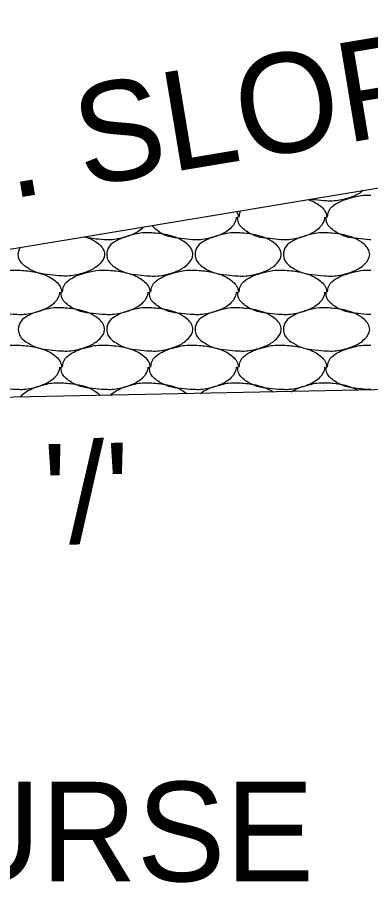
# Model space of a CAD drawing. Extents: x 1364961 to 1365294, y 367927 to 368034.
# Drawn here: x 1365019.89 to 1365021.94, y 367994.89 to 367999.9 of the extents above; entities that cross this region are included whole.
import ezdxf

# ---------------------------------------------------------------- set-up
doc = ezdxf.new("R2010")
doc.units = 0
doc.layers.add('Default', color=7, linetype='Continuous')

msp = doc.modelspace()

# ---------------------------------------------------------------- linework, layer by layer
at = {"layer": 'Default'}
for p, q in [((1365025.9943, 367999.5737), (1365004.6394, 367996.027)), ((1365019.8943, 367998.4337), (1365019.9003, 367998.4337)), ((1365020.4063, 367998.4337), (1365020.4123, 367998.4337)), ((1365020.9183, 367998.4337), (1365020.9243, 367998.4337)), ((1365021.4303, 367998.4337), (1365021.4363, 367998.4337)), ((1365019.8943, 367997.9997), (1365019.9003, 367997.9997)), ((1365020.4063, 367997.9997), (1365020.4123, 367997.9997)), ((1365020.9183, 367997.9997), (1365020.9243, 367997.9997)), ((1365021.4303, 367997.9997), (1365021.4363, 367997.9997)), ((1365031.9783, 367997.9397), (1365013.9943, 367997.5807))]:
    msp.add_line(p, q, dxfattribs=at)
for points in [[(1365021.8983, 367998.8937), (1365021.8783, 367998.8797), (1365021.8163, 367998.8517), (1365021.7303, 367998.8337), (1365021.6863, 367998.8337), (1365021.6203, 367998.8397), (1365021.5943, 367998.8427)], [(1365021.6923, 367998.7397), (1365021.6923, 367998.7417), (1365021.7083, 367998.7897), (1365021.7483, 367998.8217), (1365021.7883, 367998.8397), (1365021.8483, 367998.8577), (1365021.8863, 367998.8657), (1365021.9423, 367998.8677)], [(1365021.5833, 367998.8407), (1365021.6263, 367998.8217), (1365021.6783, 367998.7717), (1365021.6863, 367998.7417), (1365021.6863, 367998.7397)], [(1365021.1663, 367998.7717), (1365021.1743, 367998.7417), (1365021.1743, 367998.7397)], [(1365021.1803, 367998.7397), (1365021.1803, 367998.7417), (1365021.1883, 367998.7757)], [(1365021.1623, 367998.7397), (1365021.1623, 367998.7337), (1365021.1343, 367998.6797), (1365021.1043, 367998.6557), (1365021.0423, 367998.6277), (1365020.9563, 367998.6097), (1365020.9183, 367998.6097)], [(1365021.4303, 367998.6097), (1365021.4223, 367998.6097), (1365021.3563, 367998.6157), (1365021.2843, 367998.6277), (1365021.2303, 367998.6537), (1365021.1803, 367998.6997), (1365021.1723, 367998.7337), (1365021.1723, 367998.7397)], [(1365021.6743, 367998.7397), (1365021.6743, 367998.7337), (1365021.6463, 367998.6797), (1365021.6163, 367998.6557), (1365021.5543, 367998.6277), (1365021.4683, 367998.6097), (1365021.4303, 367998.6097)], [(1365021.9423, 367998.6097), (1365021.9343, 367998.6097), (1365021.8683, 367998.6157), (1365021.7963, 367998.6277), (1365021.7423, 367998.6537), (1365021.6923, 367998.6997), (1365021.6843, 367998.7337), (1365021.6843, 367998.7397)], [(1365020.6243, 367998.6817), (1365020.6223, 367998.6797), (1365020.5923, 367998.6557), (1365020.5303, 367998.6277), (1365020.4443, 367998.6097), (1365020.4063, 367998.6097)], [(1365020.6623, 367998.6497), (1365020.7503, 367998.6397), (1365020.8523, 367998.6037), (1365020.9043, 367998.5537), (1365020.9123, 367998.5237), (1365020.8843, 367998.4697), (1365020.8543, 367998.4457), (1365020.7923, 367998.4177), (1365020.7063, 367998.3997), (1365020.6623, 367998.3997), (1365020.5963, 367998.4057), (1365020.5243, 367998.4177), (1365020.4703, 367998.4437), (1365020.4203, 367998.4897), (1365020.4123, 367998.5237), (1365020.4283, 367998.5717), (1365020.4683, 367998.6037), (1365020.5083, 367998.6217), (1365020.5683, 367998.6397), (1365020.6063, 367998.6477), (1365020.6623, 367998.6497)], [(1365020.9183, 367998.6097), (1365020.9103, 367998.6097), (1365020.8443, 367998.6157), (1365020.7723, 367998.6277), (1365020.7183, 367998.6537), (1365020.6743, 367998.6897)], [(1365021.1743, 367998.6497), (1365021.2623, 367998.6397), (1365021.3643, 367998.6037), (1365021.4163, 367998.5537), (1365021.4243, 367998.5237), (1365021.3963, 367998.4697), (1365021.3663, 367998.4457), (1365021.3043, 367998.4177), (1365021.2183, 367998.3997), (1365021.1743, 367998.3997), (1365021.1083, 367998.4057), (1365021.0363, 367998.4177), (1365020.9823, 367998.4437), (1365020.9323, 367998.4897), (1365020.9243, 367998.5237), (1365020.9403, 367998.5717), (1365020.9803, 367998.6037), (1365021.0203, 367998.6217), (1365021.0803, 367998.6397), (1365021.1183, 367998.6477), (1365021.1743, 367998.6497)], [(1365021.6863, 367998.6497), (1365021.7743, 367998.6397), (1365021.8763, 367998.6037), (1365021.9283, 367998.5537), (1365021.9363, 367998.5237), (1365021.9083, 367998.4697), (1365021.8783, 367998.4457), (1365021.8163, 367998.4177), (1365021.7303, 367998.3997), (1365021.6863, 367998.3997), (1365021.6203, 367998.4057), (1365021.5483, 367998.4177), (1365021.4943, 367998.4437), (1365021.4443, 367998.4897), (1365021.4363, 367998.5237), (1365021.4523, 367998.5717), (1365021.4923, 367998.6037), (1365021.5323, 367998.6217), (1365021.5923, 367998.6397), (1365021.6303, 367998.6477), (1365021.6863, 367998.6497)], [(1365020.2893, 367998.6257), (1365020.3403, 367998.6037), (1365020.3923, 367998.5537), (1365020.4003, 367998.5237), (1365020.3723, 367998.4697), (1365020.3423, 367998.4457), (1365020.2803, 367998.4177), (1365020.1943, 367998.3997), (1365020.1503, 367998.3997), (1365020.0843, 367998.4057), (1365020.0123, 367998.4177), (1365019.9583, 367998.4437), (1365019.9083, 367998.4897), (1365019.9003, 367998.5237), (1365019.9113, 367998.5637)], [(1365020.4063, 367998.6097), (1365020.3983, 367998.6097), (1365020.3323, 367998.6157), (1365020.2773, 367998.6237)], [(1365019.6443, 367998.3057), (1365019.6443, 367998.3077), (1365019.6603, 367998.3557), (1365019.7003, 367998.3877), (1365019.7403, 367998.4057), (1365019.8003, 367998.4237), (1365019.8383, 367998.4317), (1365019.8943, 367998.4337)], [(1365019.9003, 367998.4337), (1365019.9883, 367998.4237), (1365020.0903, 367998.3877), (1365020.1423, 367998.3377), (1365020.1503, 367998.3077), (1365020.1503, 367998.3057)], [(1365020.1563, 367998.3057), (1365020.1563, 367998.3077), (1365020.1723, 367998.3557), (1365020.2123, 367998.3877), (1365020.2523, 367998.4057), (1365020.3123, 367998.4237), (1365020.3503, 367998.4317), (1365020.4063, 367998.4337)], [(1365020.4123, 367998.4337), (1365020.5003, 367998.4237), (1365020.6023, 367998.3877), (1365020.6543, 367998.3377), (1365020.6623, 367998.3077), (1365020.6623, 367998.3057)], [(1365020.6683, 367998.3057), (1365020.6683, 367998.3077), (1365020.6843, 367998.3557), (1365020.7243, 367998.3877), (1365020.7643, 367998.4057), (1365020.8243, 367998.4237), (1365020.8623, 367998.4317), (1365020.9183, 367998.4337)], [(1365020.9243, 367998.4337), (1365021.0123, 367998.4237), (1365021.1143, 367998.3877), (1365021.1663, 367998.3377), (1365021.1743, 367998.3077), (1365021.1743, 367998.3057)], [(1365021.1803, 367998.3057), (1365021.1803, 367998.3077), (1365021.1963, 367998.3557), (1365021.2363, 367998.3877), (1365021.2763, 367998.4057), (1365021.3363, 367998.4237), (1365021.3743, 367998.4317), (1365021.4303, 367998.4337)], [(1365021.4363, 367998.4337), (1365021.5243, 367998.4237), (1365021.6263, 367998.3877), (1365021.6783, 367998.3377), (1365021.6863, 367998.3077), (1365021.6863, 367998.3057)], [(1365021.6923, 367998.3057), (1365021.6923, 367998.3077), (1365021.7083, 367998.3557), (1365021.7483, 367998.3877), (1365021.7883, 367998.4057), (1365021.8483, 367998.4237), (1365021.8863, 367998.4317), (1365021.9423, 367998.4337)], [(1365019.8943, 367998.1757), (1365019.8863, 367998.1757), (1365019.8203, 367998.1817), (1365019.7483, 367998.1937), (1365019.6943, 367998.2197), (1365019.6443, 367998.2657), (1365019.6363, 367998.2997), (1365019.6363, 367998.3057)], [(1365020.1383, 367998.3057), (1365020.1383, 367998.2997), (1365020.1103, 367998.2457), (1365020.0803, 367998.2217), (1365020.0183, 367998.1937), (1365019.9323, 367998.1757), (1365019.8943, 367998.1757)], [(1365020.4063, 367998.1757), (1365020.3983, 367998.1757), (1365020.3323, 367998.1817), (1365020.2603, 367998.1937), (1365020.2063, 367998.2197), (1365020.1563, 367998.2657), (1365020.1483, 367998.2997), (1365020.1483, 367998.3057)], [(1365020.6503, 367998.3057), (1365020.6503, 367998.2997), (1365020.6223, 367998.2457), (1365020.5923, 367998.2217), (1365020.5303, 367998.1937), (1365020.4443, 367998.1757), (1365020.4063, 367998.1757)], [(1365020.9183, 367998.1757), (1365020.9103, 367998.1757), (1365020.8443, 367998.1817), (1365020.7723, 367998.1937), (1365020.7183, 367998.2197), (1365020.6683, 367998.2657), (1365020.6603, 367998.2997), (1365020.6603, 367998.3057)], [(1365021.1623, 367998.3057), (1365021.1623, 367998.2997), (1365021.1343, 367998.2457), (1365021.1043, 367998.2217), (1365021.0423, 367998.1937), (1365020.9563, 367998.1757), (1365020.9183, 367998.1757)], [(1365021.4303, 367998.1757), (1365021.4223, 367998.1757), (1365021.3563, 367998.1817), (1365021.2843, 367998.1937), (1365021.2303, 367998.2197), (1365021.1803, 367998.2657), (1365021.1723, 367998.2997), (1365021.1723, 367998.3057)], [(1365021.6743, 367998.3057), (1365021.6743, 367998.2997), (1365021.6463, 367998.2457), (1365021.6163, 367998.2217), (1365021.5543, 367998.1937), (1365021.4683, 367998.1757), (1365021.4303, 367998.1757)], [(1365021.9423, 367998.1757), (1365021.9343, 367998.1757), (1365021.8683, 367998.1817), (1365021.7963, 367998.1937), (1365021.7423, 367998.2197), (1365021.6923, 367998.2657), (1365021.6843, 367998.2997), (1365021.6843, 367998.3057)], [(1365020.1503, 367998.2157), (1365020.2383, 367998.2057), (1365020.3403, 367998.1697), (1365020.3923, 367998.1197), (1365020.4003, 367998.0897), (1365020.3723, 367998.0357), (1365020.3423, 367998.0117), (1365020.2803, 367997.9837), (1365020.1943, 367997.9657), (1365020.1503, 367997.9657), (1365020.0843, 367997.9717), (1365020.0123, 367997.9837), (1365019.9583, 367998.0097), (1365019.9083, 367998.0557), (1365019.9003, 367998.0897), (1365019.9163, 367998.1377), (1365019.9563, 367998.1697), (1365019.9963, 367998.1877), (1365020.0563, 367998.2057), (1365020.0943, 367998.2137), (1365020.1503, 367998.2157)], [(1365020.6623, 367998.2157), (1365020.7503, 367998.2057), (1365020.8523, 367998.1697), (1365020.9043, 367998.1197), (1365020.9123, 367998.0897), (1365020.8843, 367998.0357), (1365020.8543, 367998.0117), (1365020.7923, 367997.9837), (1365020.7063, 367997.9657), (1365020.6623, 367997.9657), (1365020.5963, 367997.9717), (1365020.5243, 367997.9837), (1365020.4703, 367998.0097), (1365020.4203, 367998.0557), (1365020.4123, 367998.0897), (1365020.4283, 367998.1377), (1365020.4683, 367998.1697), (1365020.5083, 367998.1877), (1365020.5683, 367998.2057), (1365020.6063, 367998.2137), (1365020.6623, 367998.2157)], [(1365021.1743, 367998.2157), (1365021.2623, 367998.2057), (1365021.3643, 367998.1697), (1365021.4163, 367998.1197), (1365021.4243, 367998.0897), (1365021.3963, 367998.0357), (1365021.3663, 367998.0117), (1365021.3043, 367997.9837), (1365021.2183, 367997.9657), (1365021.1743, 367997.9657), (1365021.1083, 367997.9717), (1365021.0363, 367997.9837), (1365020.9823, 367998.0097), (1365020.9323, 367998.0557), (1365020.9243, 367998.0897), (1365020.9403, 367998.1377), (1365020.9803, 367998.1697), (1365021.0203, 367998.1877), (1365021.0803, 367998.2057), (1365021.1183, 367998.2137), (1365021.1743, 367998.2157)], [(1365021.6863, 367998.2157), (1365021.7743, 367998.2057), (1365021.8763, 367998.1697), (1365021.9283, 367998.1197), (1365021.9363, 367998.0897), (1365021.9083, 367998.0357), (1365021.8783, 367998.0117), (1365021.8163, 367997.9837), (1365021.7303, 367997.9657), (1365021.6863, 367997.9657), (1365021.6203, 367997.9717), (1365021.5483, 367997.9837), (1365021.4943, 367998.0097), (1365021.4443, 367998.0557), (1365021.4363, 367998.0897), (1365021.4523, 367998.1377), (1365021.4923, 367998.1697), (1365021.5323, 367998.1877), (1365021.5923, 367998.2057), (1365021.6303, 367998.2137), (1365021.6863, 367998.2157)], [(1365019.6443, 367997.8717), (1365019.6443, 367997.8737), (1365019.6603, 367997.9217), (1365019.7003, 367997.9537), (1365019.7403, 367997.9717), (1365019.8003, 367997.9897), (1365019.8383, 367997.9977), (1365019.8943, 367997.9997)], [(1365019.9003, 367997.9997), (1365019.9883, 367997.9897), (1365020.0903, 367997.9537), (1365020.1423, 367997.9037), (1365020.1503, 367997.8737), (1365020.1503, 367997.8717)], [(1365020.1563, 367997.8717), (1365020.1563, 367997.8737), (1365020.1723, 367997.9217), (1365020.2123, 367997.9537), (1365020.2523, 367997.9717), (1365020.3123, 367997.9897), (1365020.3503, 367997.9977), (1365020.4063, 367997.9997)], [(1365020.4123, 367997.9997), (1365020.5003, 367997.9897), (1365020.6023, 367997.9537), (1365020.6543, 367997.9037), (1365020.6623, 367997.8737), (1365020.6623, 367997.8717)], [(1365020.6683, 367997.8717), (1365020.6683, 367997.8737), (1365020.6843, 367997.9217), (1365020.7243, 367997.9537), (1365020.7643, 367997.9717), (1365020.8243, 367997.9897), (1365020.8623, 367997.9977), (1365020.9183, 367997.9997)], [(1365020.9243, 367997.9997), (1365021.0123, 367997.9897), (1365021.1143, 367997.9537), (1365021.1663, 367997.9037), (1365021.1743, 367997.8737), (1365021.1743, 367997.8717)], [(1365021.1803, 367997.8717), (1365021.1803, 367997.8737), (1365021.1963, 367997.9217), (1365021.2363, 367997.9537), (1365021.2763, 367997.9717), (1365021.3363, 367997.9897), (1365021.3743, 367997.9977), (1365021.4303, 367997.9997)], [(1365021.4363, 367997.9997), (1365021.5243, 367997.9897), (1365021.6263, 367997.9537), (1365021.6783, 367997.9037), (1365021.6863, 367997.8737), (1365021.6863, 367997.8717)], [(1365021.6923, 367997.8717), (1365021.6923, 367997.8737), (1365021.7083, 367997.9217), (1365021.7483, 367997.9537), (1365021.7883, 367997.9717), (1365021.8483, 367997.9897), (1365021.8863, 367997.9977), (1365021.9423, 367997.9997)], [(1365019.8943, 367997.7417), (1365019.8863, 367997.7417), (1365019.8203, 367997.7477), (1365019.7483, 367997.7597), (1365019.6943, 367997.7857), (1365019.6443, 367997.8317), (1365019.6363, 367997.8657), (1365019.6363, 367997.8717)], [(1365020.1383, 367997.8717), (1365020.1383, 367997.8657), (1365020.1103, 367997.8117), (1365020.0803, 367997.7877), (1365020.0183, 367997.7597), (1365019.9323, 367997.7417), (1365019.8943, 367997.7417)], [(1365020.4063, 367997.7417), (1365020.3983, 367997.7417), (1365020.3323, 367997.7477), (1365020.2603, 367997.7597), (1365020.2063, 367997.7857), (1365020.1563, 367997.8317), (1365020.1483, 367997.8657), (1365020.1483, 367997.8717)], [(1365020.6503, 367997.8717), (1365020.6503, 367997.8657), (1365020.6223, 367997.8117), (1365020.5923, 367997.7877), (1365020.5303, 367997.7597), (1365020.4443, 367997.7417), (1365020.4063, 367997.7417)], [(1365020.9183, 367997.7417), (1365020.9103, 367997.7417), (1365020.8443, 367997.7477), (1365020.7723, 367997.7597), (1365020.7183, 367997.7857), (1365020.6683, 367997.8317), (1365020.6603, 367997.8657), (1365020.6603, 367997.8717)], [(1365021.1623, 367997.8717), (1365021.1623, 367997.8657), (1365021.1343, 367997.8117), (1365021.1043, 367997.7877), (1365021.0423, 367997.7597), (1365020.9563, 367997.7417), (1365020.9183, 367997.7417)], [(1365021.4303, 367997.7417), (1365021.4223, 367997.7417), (1365021.3563, 367997.7477), (1365021.2843, 367997.7597), (1365021.2303, 367997.7857), (1365021.1803, 367997.8317), (1365021.1723, 367997.8657), (1365021.1723, 367997.8717)], [(1365021.6743, 367997.8717), (1365021.6743, 367997.8657), (1365021.6463, 367997.8117), (1365021.6163, 367997.7877), (1365021.5543, 367997.7597), (1365021.4683, 367997.7417), (1365021.4303, 367997.7417)], [(1365021.9423, 367997.7417), (1365021.9343, 367997.7417), (1365021.8683, 367997.7477), (1365021.7963, 367997.7597), (1365021.7423, 367997.7857), (1365021.6923, 367997.8317), (1365021.6843, 367997.8657), (1365021.6843, 367997.8717)], [(1365019.9133, 367997.6987), (1365019.9163, 367997.7037), (1365019.9563, 367997.7357), (1365019.9963, 367997.7537), (1365020.0563, 367997.7717), (1365020.0943, 367997.7797), (1365020.1503, 367997.7817)], [(1365020.1503, 367997.7817), (1365020.2383, 367997.7717), (1365020.3403, 367997.7357), (1365020.3753, 367997.7077)], [(1365020.4323, 367997.7097), (1365020.4683, 367997.7357), (1365020.5083, 367997.7537), (1365020.5683, 367997.7717), (1365020.6063, 367997.7797), (1365020.6623, 367997.7817)], [(1365020.6623, 367997.7817), (1365020.7503, 367997.7717), (1365020.8523, 367997.7357), (1365020.8773, 367997.7177)], [(1365020.9553, 367997.7197), (1365020.9803, 367997.7357), (1365021.0203, 367997.7537), (1365021.0803, 367997.7717), (1365021.1183, 367997.7797), (1365021.1743, 367997.7817)], [(1365021.1743, 367997.7817), (1365021.2623, 367997.7717), (1365021.3643, 367997.7357), (1365021.3763, 367997.7277)], [(1365021.4823, 367997.7297), (1365021.4923, 367997.7357), (1365021.5323, 367997.7537), (1365021.5923, 367997.7717), (1365021.6303, 367997.7797), (1365021.6863, 367997.7817)], [(1365021.6863, 367997.7817), (1365021.7743, 367997.7717), (1365021.8723, 367997.7377)]]:
    msp.add_spline(points, degree=3, dxfattribs=at)

# ---------------------------------------------------------------- texts
for s, rotation, p in [('EXIST. SLOPE', 9.4298, (1365017.6593, 367998.481)), ("0.02 '/'", 1.1427, (1365018.3349, 367996.8152))]:
    msp.add_text(s, height=0.576, rotation=rotation, dxfattribs=at).set_placement(p)
msp.add_text('AGGREGATE BASE COURSE', height=0.576, dxfattribs=at).set_placement((1365010.9568, 367994.8955))

doc.saveas('drawing.dxf')
